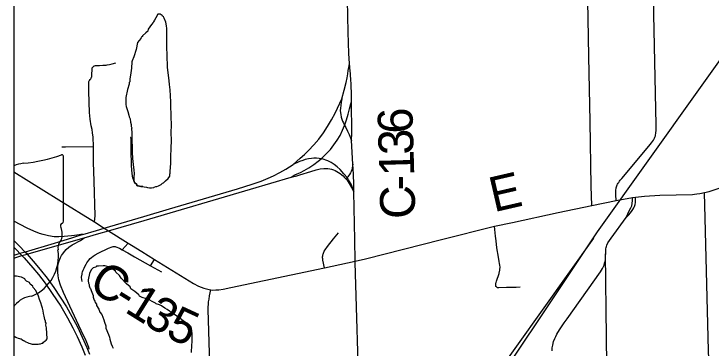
# Model space of a CAD drawing. Extents: x -12 to 34, y 0 to 22.
# Drawn here: x 2.1 to 3.233, y 15.63 to 16.174 of the extents above; entities that cross this region are included whole.
import ezdxf

# ---------------------------------------------------------------- set-up
doc = ezdxf.new("R2010")
doc.units = 0
for name, color, linetype in [('Default', 7, 'Continuous'), ('GM_X_Airport_Location_Class_2', 7, 'Continuous'), ('GM_X_Airport_Location_Class_3', 7, 'Continuous'), ('GM_X_Corporation', 7, 'Continuous'), ('GM_X_County_Road', 7, 'Continuous'), ('GM_X_Major_Lake', 7, 'Continuous'), ('GM_X_Major_River', 7, 'Continuous'), ('GM_X_Minor_Lake', 7, 'Continuous'), ('GM_X_Unincorporated_Location', 7, 'Continuous')]:
    doc.layers.add(name, color=color, linetype=linetype)

msp = doc.modelspace()

# ---------------------------------------------------------------- linework, layer by layer
at = {"layer": 'Default'}
msp.add_line((2.1, 15.9263), (2.1, 15.6975), dxfattribs=at)
msp.add_lwpolyline([(2.1807, 15.8362), (2.1807, 15.8362), (2.1808, 15.8361), (2.1808, 15.941)], dxfattribs=at)
for centre, radius, start, end in [((2.0868, 16.2087), 0.2796, 275.8445, 288.9065), ((2.1778, 15.9413), 0.00294, 355.0978, 97.738), ((2.1225, 15.8747), 0.0563, 97.3462, 113.5816), ((2.1776, 15.8357), 0.00314, 289.6038, 7.7341), ((2.1801, 15.8285), 0.00454, 107.944, 210.337), ((2.1512, 15.8152), 0.0273, 340.033, 23.6496), ((2.1913, 15.7923), 0.0198, 136.8065, 186.9296), ((2.1025, 15.779), 0.0699, 292.3089, 8.9858), ((2.132, 15.6761), 0.0383, 94.4031, 142.5768), ((2.0835, 15.7129), 0.0226, 317.0493, 323.2771)]:
    msp.add_arc(centre, radius, start, end, dxfattribs=at)
at = {"layer": 'GM_X_Airport_Location_Class_2'}
for points in [[(2.1, 20.9), (2.1, 15.613), (2.1373, 15.5975), (2.1605, 15.5875), (2.1965, 15.5592), (2.2165, 15.5455), (2.2203, 15.5426), (2.2262, 15.4696), (2.2577, 15.2632), (2.3604, 14.1215)], [(2.1, 17.9664), (2.1, 15.613), (2.1373, 15.5975), (2.1605, 15.5875), (2.1965, 15.5592), (2.2165, 15.5455), (2.2203, 15.5426), (2.2262, 15.4696), (2.2577, 15.2632), (2.3604, 14.1215)]]:
    msp.add_lwpolyline(points, dxfattribs=at)
at = {"layer": 'GM_X_Airport_Location_Class_3'}
for p, q in [((3.0398, 15.8619), (3.0792, 15.8701)), ((3.0792, 15.8701), (3.1057, 15.8746)), ((2.6047, 15.7605), (2.6549, 15.7711))]:
    msp.add_line(p, q, dxfattribs=at)
for points in [[(2.651, 15.9291), (2.6491, 15.9678), (2.6496, 15.9797), (2.6488, 16.0308)], [(2.6524, 15.8843), (2.6528, 15.8895), (2.6529, 15.8958), (2.6523, 15.913), (2.651, 15.9291)], [(2.1, 15.9164), (2.1728, 15.8712), (2.2308, 15.835)], [(3.2226, 15.883), (3.2305, 15.8848), (3.2453, 15.8895), (3.26, 15.8951)], [(2.6549, 15.7711), (2.6541, 15.806), (2.6524, 15.8843)], [(3.1057, 15.8746), (3.1068, 15.8748), (3.1109, 15.8753), (3.1254, 15.8771), (3.1503, 15.8785), (3.2032, 15.88), (3.2068, 15.8803), (3.2101, 15.8807), (3.2154, 15.8814), (3.2226, 15.883)], [(2.8816, 15.8281), (2.9105, 15.8342), (2.9847, 15.8505), (3.0398, 15.8619)], [(2.2308, 15.835), (2.2468, 15.8252), (2.2539, 15.8206), (2.2858, 15.8008)], [(2.6549, 15.7711), (2.6714, 15.7752), (2.795, 15.8065), (2.8816, 15.8281)], [(2.2858, 15.8008), (2.2914, 15.7973), (2.3078, 15.7871), (2.3287, 15.774), (2.3918, 15.7347), (2.4001, 15.7305), (2.4087, 15.7272), (2.4175, 15.7249), (2.4201, 15.7247)], [(2.6623, 15.5111), (2.6618, 15.5336), (2.655, 15.7689), (2.6549, 15.7711)], [(2.4201, 15.7247), (2.4236, 15.7243), (2.4283, 15.7245), (2.4331, 15.7248), (2.44, 15.7259), (2.4524, 15.7284), (2.6047, 15.7605)]]:
    msp.add_lwpolyline(points, dxfattribs=at)
at = {"layer": 'GM_X_Corporation'}
msp.add_lwpolyline([(2.8614, 14.9446), (2.8237, 15.0402), (2.7924, 15.0967), (2.7435, 15.1932), (2.7326, 15.2135), (2.7266, 15.2424), (2.7245, 15.2828), (2.7326, 15.3249), (2.7503, 15.3643), (2.8291, 15.4899), (3.0486, 15.8188), (3.3759, 16.2779), (3.6102, 16.618), (3.6764, 16.6954), (3.7218, 16.7297), (3.762, 16.7538), (3.8349, 16.7817), (3.8869, 16.8002), (4.008, 16.8225), (4.8175, 16.8457)], dxfattribs=at)
at = {"layer": 'GM_X_Major_Lake'}
for p, q in [((2.1, 15.7936), (2.1001, 15.7934)), ((2.1001, 15.7934), (2.105, 15.7885))]:
    msp.add_line(p, q, dxfattribs=at)
for points in [[(2.6436, 16.1442), (2.6423, 16.1961), (2.6419, 16.2178), (2.64, 16.2643), (2.6377, 16.3543), (2.6356, 16.4641)], [(2.6488, 16.0308), (2.6486, 16.042), (2.6483, 16.0589), (2.6478, 16.0677), (2.6475, 16.0733), (2.6471, 16.0767), (2.6467, 16.0803), (2.6454, 16.0932), (2.6446, 16.1092), (2.6436, 16.1442)], [(2.2122, 15.8145), (2.2342, 15.8213), (2.2468, 15.8252), (2.3114, 15.8441), (2.3532, 15.8564), (2.4635, 15.889), (2.4872, 15.8965), (2.5019, 15.9017), (2.5135, 15.9063), (2.522, 15.9103), (2.5324, 15.9156), (2.5421, 15.9212), (2.5538, 15.9288), (2.5655, 15.939), (2.5723, 15.9451), (2.579, 15.9515), (2.5876, 15.9606), (2.5956, 15.97), (2.6032, 15.9799), (2.6101, 15.9903), (2.6165, 16.001), (2.6222, 16.012), (2.6261, 16.0205), (2.6333, 16.0355), (2.6372, 16.0497), (2.6403, 16.062), (2.6419, 16.0695), (2.643, 16.0763), (2.6437, 16.0814), (2.6445, 16.0863), (2.6454, 16.0932)], [(2.5509, 15.9082), (2.5567, 15.9115), (2.5603, 15.9132), (2.5659, 15.9158), (2.5719, 15.9186), (2.5796, 15.9234), (2.5874, 15.9284), (2.5948, 15.9339), (2.5996, 15.938), (2.6018, 15.9398), (2.6084, 15.9463), (2.6146, 15.9531), (2.6204, 15.9603), (2.6256, 15.968), (2.6302, 15.976), (2.6343, 15.9842), (2.6377, 15.9922), (2.638, 15.9932), (2.641, 16.0014), (2.6435, 16.0103), (2.6458, 16.0189), (2.6479, 16.0274), (2.6488, 16.0308)], [(2.214, 15.8092), (2.2381, 15.8161), (2.2539, 15.8206), (2.312, 15.8374), (2.4846, 15.8882), (2.5509, 15.9082)], [(2.1, 15.8047), (2.1087, 15.796), (2.1185, 15.786), (2.1202, 15.7843), (2.1216, 15.7828), (2.1314, 15.7715), (2.1429, 15.7579), (2.1542, 15.7435), (2.165, 15.7284), (2.1754, 15.7129), (2.1852, 15.6971), (2.1944, 15.681), (2.2031, 15.6645), (2.2111, 15.6477), (2.2185, 15.6307), (2.2226, 15.6199)], [(2.2223, 15.6282), (2.2216, 15.6308), (2.2172, 15.6415), (2.2094, 15.6585), (2.1907, 15.6978), (2.1804, 15.7205), (2.1759, 15.7321), (2.1731, 15.741), (2.1718, 15.7471), (2.1711, 15.7533), (2.1711, 15.7595), (2.1714, 15.7626), (2.1719, 15.7657), (2.1726, 15.7687), (2.1735, 15.7717), (2.1745, 15.7746), (2.1758, 15.7774), (2.1773, 15.7802), (2.1789, 15.7828), (2.1828, 15.7877), (2.1849, 15.79), (2.1895, 15.7941), (2.1946, 15.7977), (2.2, 15.8008), (2.2039, 15.8028), (2.2082, 15.8049), (2.21, 15.8059), (2.2121, 15.8074), (2.214, 15.8092)], [(2.105, 15.7885), (2.1098, 15.7835), (2.113, 15.7802), (2.1164, 15.7767), (2.1307, 15.7606), (2.1398, 15.7497), (2.1505, 15.7354), (2.162, 15.7187), (2.1763, 15.6982), (2.187, 15.6792), (2.1958, 15.6627), (2.2026, 15.6487), (2.2102, 15.6316), (2.2158, 15.6184)]]:
    msp.add_lwpolyline(points, dxfattribs=at)
at = {"layer": 'GM_X_Major_River'}
for p, q in [((2.2762, 15.7898), (2.2858, 15.8008)), ((2.3223, 15.7635), (2.3287, 15.774)), ((2.3223, 15.7635), (2.3398, 15.7539))]:
    msp.add_line(p, q, dxfattribs=at)
for points in [[(3.0398, 15.8619), (3.0388, 15.8935), (3.0369, 15.9988), (3.0348, 16.1041), (3.0337, 16.1661), (3.0332, 16.1939), (3.0321, 16.2559), (3.0321, 16.259)], [(3.0792, 15.8701), (3.0788, 15.8792), (3.0788, 15.8846), (3.0789, 15.8873), (3.079, 15.8893), (3.0793, 15.8907), (3.0797, 15.8924), (3.0802, 15.8937), (3.0809, 15.8954), (3.0814, 15.8965), (3.0824, 15.8981), (3.0833, 15.8993), (3.0848, 15.9015), (3.0857, 15.9028), (3.0882, 15.9058), (3.1107, 15.9326), (3.1346, 15.9609), (3.1368, 15.9637), (3.1385, 15.9662), (3.1398, 15.9684), (3.1408, 15.9701), (3.1414, 15.9715), (3.1421, 15.9731), (3.1429, 15.9752), (3.1433, 15.9768), (3.1437, 15.979), (3.1439, 15.9807), (3.1442, 15.9836), (3.1444, 15.9873), (3.1445, 15.9929), (3.1407, 16.1727), (3.1407, 16.1926)], [(2.2266, 16.0724), (2.2268, 16.0744), (2.2269, 16.0778), (2.227, 16.0803), (2.227, 16.0822), (2.227, 16.0835), (2.227, 16.0846), (2.2272, 16.0853), (2.2274, 16.0859), (2.2281, 16.087), (2.2288, 16.0878), (2.2293, 16.0883), (2.2302, 16.089), (2.2311, 16.0894), (2.2324, 16.0897), (2.2334, 16.0898), (2.2352, 16.0899), (2.2392, 16.0899), (2.2447, 16.0901), (2.2474, 16.0902), (2.2499, 16.0904), (2.2517, 16.0906), (2.2554, 16.0912), (2.2599, 16.0923), (2.2658, 16.0938)], [(2.2292, 15.9579), (2.2287, 15.9733), (2.228, 15.9801), (2.2271, 15.9856), (2.2258, 15.9916), (2.2239, 16.0026), (2.2233, 16.0077), (2.2231, 16.0133), (2.222, 16.0476), (2.2219, 16.0539), (2.2217, 16.0602), (2.2217, 16.0615), (2.2218, 16.0626), (2.222, 16.0637), (2.2224, 16.0647), (2.2229, 16.0655), (2.2239, 16.0669), (2.2251, 16.068), (2.2258, 16.0693), (2.2262, 16.0705), (2.2264, 16.0713), (2.2266, 16.0724)], [(2.1779, 15.9575), (2.1839, 15.9573), (2.2292, 15.9579)], [(2.2308, 15.835), (2.2314, 15.8402), (2.2318, 15.845), (2.2305, 15.9017), (2.2295, 15.9321), (2.2292, 15.9579)], [(3.1982, 15.4744), (3.1989, 15.4757), (3.213, 15.4999), (3.2225, 15.5161), (3.229, 15.5279), (3.2307, 15.532), (3.2317, 15.535), (3.2322, 15.5374), (3.2326, 15.54), (3.2326, 15.5434), (3.232, 15.5576), (3.2308, 15.5856), (3.2295, 15.6261), (3.224, 15.8412), (3.2226, 15.883)], [(3.0956, 15.8421), (3.1, 15.8467), (3.1043, 15.8521), (3.1064, 15.8551), (3.1078, 15.8579), (3.1089, 15.8601), (3.1099, 15.8632), (3.1104, 15.8668), (3.1108, 15.8712), (3.1109, 15.8753)], [(3.0956, 15.8421), (3.101, 15.8542), (3.1032, 15.8583), (3.1047, 15.8614), (3.1053, 15.8653), (3.1057, 15.87), (3.1057, 15.8746)], [(2.9752, 15.6252), (2.9754, 15.6301), (2.976, 15.6345), (2.9773, 15.6405), (2.9793, 15.6454), (2.981, 15.6487), (2.9827, 15.6523), (2.9872, 15.6596), (2.9949, 15.6707), (2.9997, 15.6776), (3.0536, 15.7538), (3.0569, 15.7591), (3.0595, 15.7647), (3.0605, 15.7678), (3.0612, 15.7707), (3.0616, 15.774), (3.0619, 15.7768), (3.0623, 15.7862), (3.0624, 15.7884), (3.0626, 15.7911), (3.0629, 15.7934), (3.0635, 15.7953), (3.0642, 15.7974), (3.0659, 15.801), (3.0708, 15.8089), (3.0956, 15.8421)], [(2.923, 15.7288), (2.9167, 15.7285), (2.9011, 15.7282), (2.8885, 15.7277), (2.8871, 15.7279), (2.8864, 15.728), (2.8857, 15.7282), (2.8851, 15.7285), (2.8844, 15.7293), (2.8838, 15.7301), (2.8834, 15.7312), (2.8833, 15.732), (2.8834, 15.7327), (2.8836, 15.7345), (2.8838, 15.7356), (2.8841, 15.7365), (2.8848, 15.7387), (2.8889, 15.7514), (2.8897, 15.755), (2.89, 15.7561), (2.8901, 15.7575), (2.8904, 15.7614), (2.8901, 15.7645), (2.8897, 15.7672), (2.8891, 15.7705), (2.8878, 15.7776), (2.8853, 15.7931), (2.8839, 15.8043), (2.883, 15.8121), (2.8816, 15.8281)], [(2.6047, 15.7605), (2.6023, 15.7731), (2.602, 15.7752), (2.6019, 15.7769), (2.6019, 15.7783), (2.602, 15.7798), (2.6023, 15.7815), (2.6026, 15.7827), (2.6031, 15.7845), (2.6044, 15.7873), (2.606, 15.7898), (2.6097, 15.7951), (2.6196, 15.8074), (2.6276, 15.8171)], [(2.2111, 15.7383), (2.2103, 15.7414), (2.21, 15.7445), (2.2101, 15.7461), (2.2102, 15.7476), (2.2107, 15.7502), (2.2111, 15.7518), (2.2116, 15.7537), (2.2128, 15.7567), (2.214, 15.7598), (2.2153, 15.7624), (2.2174, 15.7661), (2.2187, 15.7686), (2.22, 15.7705), (2.2216, 15.7728), (2.224, 15.7754), (2.2259, 15.7772), (2.2287, 15.7795), (2.2319, 15.7818), (2.2367, 15.7844), (2.2538, 15.7923), (2.2597, 15.7946), (2.2612, 15.7949), (2.2627, 15.7951), (2.2644, 15.795), (2.2658, 15.7948), (2.2716, 15.7923), (2.2762, 15.7898)], [(2.2762, 15.7898), (2.2853, 15.7848), (2.296, 15.7781), (2.3223, 15.7635)], [(2.6161, 14.5388), (2.6127, 14.5539), (2.5651, 14.7631), (2.5566, 14.8058), (2.5108, 15.009), (2.4645, 15.2121), (2.4511, 15.2665), (2.4496, 15.2749), (2.4339, 15.3423), (2.4279, 15.3728), (2.4256, 15.3912), (2.4243, 15.413), (2.4236, 15.4371), (2.4212, 15.5155), (2.4158, 15.6925), (2.4165, 15.705), (2.4172, 15.7095), (2.418, 15.7148), (2.4201, 15.7247)]]:
    msp.add_lwpolyline(points, dxfattribs=at)
at = {"layer": 'GM_X_Minor_Lake'}
for points in [[(2.3094, 15.8925), (2.3117, 15.892), (2.3158, 15.8916), (2.3173, 15.8912), (2.3204, 15.8908), (2.3234, 15.8907), (2.3272, 15.8914), (2.328, 15.8918), (2.3306, 15.8925), (2.3325, 15.8929), (2.3352, 15.8936), (2.3394, 15.8962), (2.3417, 15.8981), (2.3432, 15.8988), (2.344, 15.8999), (2.3463, 15.9022), (2.3509, 15.9059), (2.3533, 15.9097), (2.3537, 15.9131), (2.3541, 15.9146), (2.3541, 15.9173), (2.3551, 15.9309), (2.3553, 15.9435), (2.3558, 15.9522), (2.356, 15.9704), (2.3558, 15.978), (2.356, 15.9951), (2.3558, 16.0038), (2.3555, 16.013), (2.3553, 16.0198), (2.355, 16.0308), (2.3538, 16.0502), (2.3528, 16.0589), (2.3525, 16.0646), (2.3511, 16.0738), (2.3498, 16.0863), (2.3495, 16.0917), (2.3489, 16.1015), (2.349, 16.1076), (2.3487, 16.1186), (2.3486, 16.1312), (2.3487, 16.141), (2.3485, 16.1498), (2.3481, 16.1543), (2.3467, 16.1601), (2.3442, 16.1669), (2.3434, 16.1688), (2.3415, 16.17), (2.3412, 16.1711), (2.3378, 16.1731), (2.3351, 16.1735), (2.334, 16.1731), (2.3309, 16.1675), (2.3286, 16.1633), (2.327, 16.1607), (2.3266, 16.1596), (2.3235, 16.1566), (2.3185, 16.1487), (2.3177, 16.1457), (2.3142, 16.1427), (2.3092, 16.1382), (2.3088, 16.137), (2.3069, 16.1359), (2.3061, 16.1337), (2.3007, 16.1269), (2.299, 16.1159), (2.2947, 16.1038), (2.2923, 16.0974), (2.2919, 16.0959), (2.2914, 16.0856), (2.2893, 16.0739), (2.2885, 16.0678), (2.2884, 16.0629), (2.2876, 16.0621), (2.2872, 16.0595), (2.2848, 16.0504), (2.282, 16.0375), (2.2818, 16.0281), (2.2822, 16.0261), (2.2825, 16.0231), (2.285, 16.0147), (2.2868, 16.0086), (2.2876, 16.0063), (2.289, 16.0029), (2.2893, 15.9972), (2.2904, 15.9937), (2.2907, 15.9903), (2.2915, 15.988), (2.2914, 15.9865), (2.2917, 15.9808), (2.2919, 15.9687), (2.2921, 15.955), (2.2924, 15.9485), (2.293, 15.9383), (2.294, 15.9284), (2.295, 15.9192), (2.295, 15.9177), (2.2953, 15.9154), (2.2953, 15.9139), (2.2948, 15.9082), (2.2948, 15.906)], [(2.3094, 15.8925), (2.3083, 15.8929), (2.3064, 15.8929), (2.3041, 15.8933), (2.3022, 15.8937), (2.3011, 15.8937), (2.2999, 15.8945), (2.2996, 15.896), (2.2959, 15.8995), (2.2948, 15.9025), (2.2933, 15.9071), (2.293, 15.9098), (2.2923, 15.9147), (2.2916, 15.9193), (2.2913, 15.9273), (2.2914, 15.9296), (2.291, 15.9322), (2.2905, 15.947), (2.2908, 15.966), (2.2904, 15.9672), (2.2904, 15.9691), (2.2901, 15.9725), (2.2897, 15.9725)], [(2.2948, 15.906), (2.2948, 15.9025), (2.2959, 15.8995), (2.2996, 15.896), (2.2999, 15.8945), (2.3011, 15.8937), (2.3022, 15.8937), (2.3041, 15.8933), (2.3064, 15.8929), (2.3083, 15.8929), (2.3094, 15.8925)], [(3.0421, 15.8084), (2.8336, 15.5155)], [(3.0612, 15.783), (3.0648, 15.512)], [(2.3887, 15.6623), (2.3883, 15.6635), (2.3879, 15.6639), (2.3872, 15.6654), (2.3849, 15.6666), (2.3842, 15.6677), (2.3804, 15.67), (2.3786, 15.672), (2.3759, 15.6735), (2.3722, 15.6762), (2.3688, 15.6789), (2.3651, 15.6817), (2.3609, 15.6844), (2.3568, 15.6875), (2.3531, 15.6898), (2.3489, 15.6925), (2.3455, 15.6945), (2.3399, 15.6983), (2.3365, 15.6999), (2.3312, 15.7019), (2.3301, 15.703), (2.326, 15.705), (2.3196, 15.7081), (2.3177, 15.7085), (2.3154, 15.7097), (2.3083, 15.7121), (2.3041, 15.7144), (2.303, 15.7167), (2.2963, 15.7217), (2.2903, 15.726), (2.2888, 15.7294), (2.2828, 15.7345), (2.2742, 15.7433), (2.2716, 15.7479), (2.2656, 15.7533), (2.2649, 15.7552), (2.2593, 15.7591), (2.2548, 15.7615), (2.2502, 15.763), (2.248, 15.7634), (2.2453, 15.7635), (2.2377, 15.7632), (2.2343, 15.7629), (2.2339, 15.7621), (2.2324, 15.7614), (2.2286, 15.7603), (2.2274, 15.7588), (2.2255, 15.7573), (2.2231, 15.7513), (2.2207, 15.741), (2.2207, 15.7391), (2.2214, 15.7357), (2.2225, 15.7334), (2.2225, 15.7311), (2.2236, 15.7281), (2.2247, 15.7266), (2.225, 15.725), (2.2258, 15.7235), (2.228, 15.7182), (2.2287, 15.7155), (2.229, 15.7128), (2.2305, 15.7079), (2.2316, 15.7063), (2.2319, 15.7048), (2.2323, 15.7037), (2.2342, 15.701), (2.2345, 15.6991), (2.2378, 15.693), (2.2393, 15.6899), (2.2397, 15.6884), (2.243, 15.6845), (2.2459, 15.6757), (2.247, 15.6719), (2.2492, 15.6662), (2.2495, 15.6624), (2.2535, 15.6517), (2.2554, 15.6475), (2.2557, 15.6441), (2.2568, 15.6403), (2.2582, 15.6368), (2.2597, 15.633), (2.2612, 15.6296)], [(2.1541, 15.6448), (2.1528, 15.663), (2.1521, 15.6672), (2.1522, 15.6702), (2.1514, 15.6718), (2.1511, 15.6737), (2.1504, 15.6763), (2.1493, 15.6817), (2.1482, 15.6862), (2.1475, 15.6904), (2.1465, 15.6946), (2.1454, 15.6981), (2.1436, 15.7034), (2.1418, 15.7091), (2.1399, 15.7141), (2.1355, 15.7233), (2.1314, 15.7283), (2.1307, 15.7305), (2.1262, 15.7337), (2.1255, 15.7363), (2.1206, 15.7387), (2.1183, 15.7406), (2.1176, 15.7425), (2.1123, 15.7452), (2.1089, 15.746), (2.1067, 15.7465), (2.104, 15.7469), (2.1, 15.7469)], [(2.3885, 15.6225), (2.3894, 15.6346), (2.3899, 15.6399), (2.3896, 15.6471), (2.3897, 15.6536), (2.3887, 15.6623)], [(2.1, 15.649), (2.1003, 15.649), (2.1033, 15.6474), (2.1041, 15.647), (2.1071, 15.6458), (2.1093, 15.6454), (2.1105, 15.645), (2.1108, 15.6446), (2.1116, 15.6446), (2.1131, 15.6435), (2.1157, 15.6423), (2.1172, 15.6415), (2.1172, 15.6411), (2.1195, 15.6399), (2.1221, 15.6388), (2.1244, 15.6376), (2.1263, 15.6372), (2.1278, 15.6368), (2.1297, 15.6364), (2.1323, 15.6363), (2.1346, 15.6359), (2.1357, 15.6359), (2.1373, 15.6363), (2.1395, 15.6362), (2.1418, 15.6366), (2.1433, 15.6369), (2.146, 15.6377), (2.1472, 15.638), (2.1483, 15.6392), (2.151, 15.6414), (2.1525, 15.6429), (2.1541, 15.6448)]]:
    msp.add_lwpolyline(points, dxfattribs=at)
at = {"layer": 'GM_X_Unincorporated_Location'}
for points in [[(2.6333, 16.0355), (2.6323, 16.0302), (2.6313, 16.0247), (2.6309, 16.0202), (2.6307, 16.0166), (2.6308, 16.0128), (2.6313, 16.0099), (2.6323, 16.0055), (2.6332, 16.0022), (2.6343, 15.9993), (2.6357, 15.9963), (2.6377, 15.9922), (2.6381, 15.9914), (2.6395, 15.9889), (2.6424, 15.9828), (2.6449, 15.9776), (2.6491, 15.9678)], [(2.6524, 15.8843), (2.6512, 15.889), (2.6501, 15.8924), (2.6488, 15.8955), (2.6457, 15.9009), (2.6439, 15.9037), (2.6416, 15.9075), (2.6365, 15.9133), (2.6302, 15.9202), (2.6258, 15.9245), (2.6209, 15.9284), (2.6157, 15.9318), (2.6102, 15.9346), (2.6073, 15.9358), (2.6044, 15.9368), (2.6014, 15.9376), (2.5996, 15.938), (2.5964, 15.9384), (2.5922, 15.9388), (2.5878, 15.9387), (2.5836, 15.9385), (2.579, 15.9379), (2.5736, 15.9366), (2.5695, 15.9353), (2.5644, 15.9333), (2.5538, 15.9288)], [(2.651, 15.9291), (2.6501, 15.9233), (2.6497, 15.9214), (2.6492, 15.9197), (2.6483, 15.9174), (2.6471, 15.9148), (2.6456, 15.9123), (2.644, 15.9101), (2.6429, 15.9087), (2.6416, 15.9075), (2.6396, 15.9055)], [(2.5509, 15.9082), (2.5602, 15.9103), (2.5646, 15.9116), (2.5825, 15.9174), (2.5916, 15.92), (2.5977, 15.9213), (2.604, 15.922), (2.6071, 15.922), (2.6103, 15.9218), (2.6134, 15.9214), (2.6165, 15.9207), (2.6195, 15.9198), (2.6224, 15.9186), (2.6252, 15.9172), (2.6279, 15.9156), (2.6305, 15.9139), (2.633, 15.9119), (2.6352, 15.91), (2.6376, 15.9076), (2.6396, 15.9055), (2.6417, 15.9028), (2.6435, 15.9002), (2.6451, 15.8975), (2.6489, 15.891), (2.6524, 15.8843)], [(2.2122, 15.8145), (2.2089, 15.8146), (2.206, 15.8143), (2.1984, 15.813), (2.1935, 15.8123), (2.1878, 15.8117), (2.1815, 15.8113), (2.1728, 15.8109), (2.1656, 15.811), (2.1564, 15.8125), (2.1473, 15.8146), (2.1413, 15.8165), (2.1326, 15.8198), (2.1214, 15.8251), (2.1, 15.8362)], [(2.2122, 15.8145), (2.195, 15.8092), (2.1795, 15.8045), (2.1653, 15.7999), (2.1185, 15.786), (2.1098, 15.7835), (2.1, 15.7806)], [(2.1, 15.7763), (2.113, 15.7802), (2.1216, 15.7828), (2.1285, 15.7848), (2.214, 15.8092)]]:
    msp.add_lwpolyline(points, dxfattribs=at)

# ---------------------------------------------------------------- texts
at = {"layer": 'GM_X_County_Road'}
for s, rotation, p in [('6', 91.6237, (2.749, 15.9797)), ('3', 91.6161, (2.75, 15.945)), ('1', 91.5947, (2.751, 15.9103)), ('E', 13.0063, (2.8804, 15.8507)), ('-', 91.5593, (2.7516, 15.8871)), ('C', 91.4928, (2.7528, 15.8407)), ('C', 327.916, (2.2189, 15.7268)), ('-', 327.9347, (2.2584, 15.702)), ('1', 327.9966, (2.2782, 15.6896)), ('3', 328.2523, (2.3082, 15.6709)), ('5', 335.2348, (2.3446, 15.6489))]:
    msp.add_text(s, height=0.0568, rotation=rotation, dxfattribs=at).set_placement(p)

doc.saveas('drawing.dxf')
